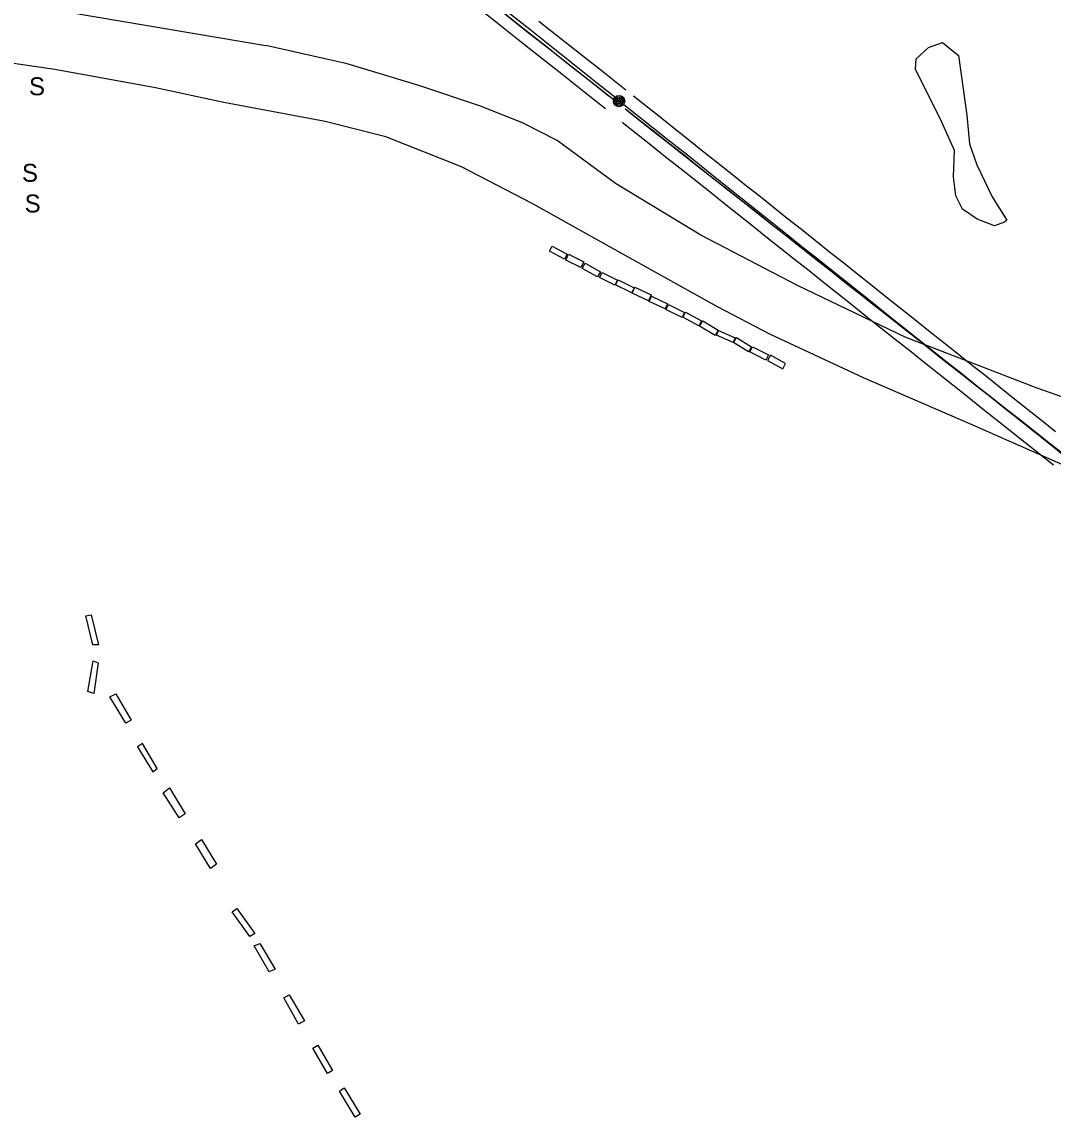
# Model space of a CAD drawing. Extents: x 368532 to 392481, y 10654822 to 10676899.
# Drawn here: x 372438.5 to 372783.2, y 10672184.9 to 10672551 of the extents above; entities that cross this region are included whole.
import ezdxf

# ---------------------------------------------------------------- set-up
doc = ezdxf.new("R2010")
doc.units = 0
for name, color, linetype in [('p_Catenary', 7, 'Continuous'), ('p_road conc barrier', 7, 'Continuous'), ('p_road dirt road', 7, 'Continuous'), ('p_structure sign', 7, 'Continuous'), ('p_utility general pole', 7, 'Continuous'), ('p_veg woods', 7, 'Continuous')]:
    doc.layers.add(name, color=color, linetype=linetype)

msp = doc.modelspace()

# ---------------------------------------------------------------- linework, layer by layer
at = {"layer": 'p_Catenary'}
for points in [[(372589.86, 10672556.62), (372597.14, 10672550.86), (372604.42, 10672545.1), (372611.7, 10672539.34), (372618.97, 10672533.59), (372626.25, 10672527.83), (372633.53, 10672522.07)], [(372598.88, 10672554.61), (372606.07, 10672548.92), (372613.25, 10672543.24), (372620.44, 10672537.55), (372627.62, 10672531.86), (372634.81, 10672526.18)], [(372599.9, 10672553.62), (372607.2, 10672547.88), (372614.51, 10672542.14), (372621.81, 10672536.41), (372629.12, 10672530.67), (372636.42, 10672524.94)], [(372601.61, 10672553.79), (372608.83, 10672548.05), (372616.04, 10672542.32), (372623.26, 10672536.58), (372630.48, 10672530.84), (372637.69, 10672525.1)], [(372611.33, 10672551.21), (372618.6, 10672545.48), (372625.88, 10672539.74), (372633.15, 10672534.01), (372640.42, 10672528.27)], [(372642.96, 10672526.25), (372651.83, 10672519.2), (372656.56, 10672515.44), (372661.28, 10672511.69), (372666, 10672507.93), (372670.72, 10672504.18), (372675.44, 10672500.42), (372680.16, 10672496.67), (372684.88, 10672492.91), (372689.61, 10672489.16), (372694.33, 10672485.4), (372699.05, 10672481.65), (372703.77, 10672477.89), (372708.49, 10672474.14), (372713.21, 10672470.38), (372717.94, 10672466.63), (372722.66, 10672462.87), (372727.38, 10672459.11), (372732.1, 10672455.36), (372736.82, 10672451.6), (372741.54, 10672447.85), (372746.27, 10672444.09), (372750.99, 10672440.34), (372755.71, 10672436.58), (372760.43, 10672432.83), (372765.15, 10672429.07), (372769.87, 10672425.32), (372774.6, 10672421.56), (372779.32, 10672417.81), (372784.04, 10672414.05)], [(372639.71, 10672523.41), (372644.63, 10672519.49), (372649.54, 10672515.57), (372654.46, 10672511.65), (372659.37, 10672507.73), (372664.28, 10672503.82), (372669.2, 10672499.9), (372674.11, 10672495.98), (372679.03, 10672492.06), (372683.94, 10672488.14), (372688.86, 10672484.22), (372693.77, 10672480.31), (372698.68, 10672476.39), (372703.6, 10672472.47), (372708.51, 10672468.55), (372713.43, 10672464.63), (372718.34, 10672460.72), (372723.26, 10672456.8), (372728.17, 10672452.88), (372733.09, 10672448.96), (372738, 10672445.04), (372742.91, 10672441.12), (372747.83, 10672437.21), (372752.74, 10672433.29), (372757.66, 10672429.37), (372762.57, 10672425.45), (372767.49, 10672421.53), (372772.4, 10672417.62), (372777.31, 10672413.7), (372782.23, 10672409.78), (372787.14, 10672405.86)], [(372640.14, 10672521.87), (372645.05, 10672518.01), (372649.95, 10672514.15), (372654.85, 10672510.29), (372659.75, 10672506.43), (372664.65, 10672502.57), (372669.56, 10672498.72), (372674.46, 10672494.86), (372679.36, 10672491), (372684.26, 10672487.14), (372689.16, 10672483.28), (372694.07, 10672479.42), (372698.97, 10672475.56), (372703.87, 10672471.71), (372708.77, 10672467.85), (372713.67, 10672463.99), (372718.58, 10672460.13), (372723.48, 10672456.27), (372728.38, 10672452.41), (372733.28, 10672448.56), (372738.18, 10672444.7), (372743.08, 10672440.84), (372747.99, 10672436.98), (372752.89, 10672433.12), (372757.79, 10672429.26), (372762.69, 10672425.4), (372767.59, 10672421.55), (372772.5, 10672417.69), (372777.4, 10672413.83), (372782.3, 10672409.97), (372787.2, 10672406.11)], [(372786.84, 10672406.15), (372781.96, 10672410), (372777.08, 10672413.85), (372772.2, 10672417.7), (372767.32, 10672421.55), (372762.44, 10672425.4), (372757.56, 10672429.25), (372752.67, 10672433.1), (372747.79, 10672436.95), (372742.91, 10672440.81), (372738.03, 10672444.66), (372733.15, 10672448.51), (372728.27, 10672452.36), (372723.39, 10672456.21), (372718.5, 10672460.06), (372713.62, 10672463.91), (372708.74, 10672467.76), (372703.86, 10672471.61), (372698.98, 10672475.46), (372694.1, 10672479.31), (372689.22, 10672483.16), (372684.33, 10672487.01), (372679.45, 10672490.86), (372674.57, 10672494.71), (372669.69, 10672498.56), (372664.81, 10672502.41), (372659.93, 10672506.26), (372655.05, 10672510.11), (372650.16, 10672513.97), (372645.28, 10672517.82), (372640.4, 10672521.67)], [(372639.15, 10672517.47), (372643.95, 10672513.65), (372648.76, 10672509.84), (372653.56, 10672506.02), (372658.37, 10672502.2), (372663.17, 10672498.38), (372667.98, 10672494.56), (372672.78, 10672490.74), (372677.58, 10672486.92), (372682.39, 10672483.1), (372687.19, 10672479.28), (372692, 10672475.46), (372696.8, 10672471.64), (372701.61, 10672467.82), (372706.41, 10672464), (372711.22, 10672460.18), (372716.02, 10672456.36), (372720.83, 10672452.55), (372725.63, 10672448.73), (372730.43, 10672444.91), (372735.24, 10672441.09), (372740.04, 10672437.27), (372744.85, 10672433.45), (372749.65, 10672429.63), (372754.46, 10672425.81), (372759.26, 10672421.99), (372764.07, 10672418.17), (372768.87, 10672414.35), (372773.68, 10672410.53), (372778.48, 10672406.71), (372783.28, 10672402.89)]]:
    msp.add_lwpolyline(points, dxfattribs=at)
at = {"layer": 'p_road conc barrier'}
for p, q in [((372614.82, 10672474.29), (372615.72, 10672475.99)), ((372619.84, 10672471.62), (372614.82, 10672474.29)), ((372615.72, 10672475.99), (372620.74, 10672473.32)), ((372620.74, 10672473.32), (372619.84, 10672471.62)), ((372620.26, 10672471.36), (372621.23, 10672473.29)), ((372625.3, 10672468.83), (372620.26, 10672471.36)), ((372621.23, 10672473.29), (372626.28, 10672470.76)), ((372626.28, 10672470.76), (372625.3, 10672468.83)), ((372625.78, 10672468.57), (372626.75, 10672470.3)), ((372626.75, 10672470.3), (372631.85, 10672467.45)), ((372630.88, 10672465.72), (372625.78, 10672468.57)), ((372631.85, 10672467.45), (372630.88, 10672465.72)), ((372631.6, 10672465.55), (372632.45, 10672467.23)), ((372632.45, 10672467.23), (372637.55, 10672464.64)), ((372636.69, 10672462.96), (372631.6, 10672465.55)), ((372637.55, 10672464.64), (372636.69, 10672462.96)), ((372636.96, 10672463.07), (372637.82, 10672464.79)), ((372642.32, 10672460.38), (372636.96, 10672463.07)), ((372637.82, 10672464.79), (372643.18, 10672462.1)), ((372643.18, 10672462.1), (372642.32, 10672460.38)), ((372642.5, 10672460.31), (372643.41, 10672462.26)), ((372647.91, 10672457.78), (372642.5, 10672460.31)), ((372643.41, 10672462.26), (372648.82, 10672459.73)), ((372648.82, 10672459.73), (372647.91, 10672457.78)), ((372648.18, 10672457.52), (372648.99, 10672459.25)), ((372648.99, 10672459.25), (372654.29, 10672456.77)), ((372653.49, 10672455.04), (372648.18, 10672457.52)), ((372654.29, 10672456.77), (372653.49, 10672455.04)), ((372653.78, 10672454.86), (372654.59, 10672456.5)), ((372654.59, 10672456.5), (372659.97, 10672453.84)), ((372659.17, 10672452.2), (372653.78, 10672454.86)), ((372659.97, 10672453.84), (372659.17, 10672452.2)), ((372659.45, 10672452.28), (372660.34, 10672453.9)), ((372664.77, 10672449.38), (372659.45, 10672452.28)), ((372660.34, 10672453.9), (372665.65, 10672451)), ((372665.65, 10672451), (372664.77, 10672449.38)), ((372664.98, 10672449.23), (372666.05, 10672451.04)), ((372670.22, 10672446.14), (372664.98, 10672449.23)), ((372666.05, 10672451.04), (372671.28, 10672447.96)), ((372671.28, 10672447.96), (372670.22, 10672446.14)), ((372670.64, 10672446.26), (372671.34, 10672447.84)), ((372676.2, 10672443.78), (372670.64, 10672446.26)), ((372671.34, 10672447.84), (372676.91, 10672445.37)), ((372676.91, 10672445.37), (372676.2, 10672443.78)), ((372676.33, 10672443.81), (372677.35, 10672445.46)), ((372677.35, 10672445.46), (372682.37, 10672442.37)), ((372681.36, 10672440.72), (372676.33, 10672443.81)), ((372682.37, 10672442.37), (372681.36, 10672440.72)), ((372681.84, 10672440.63), (372682.71, 10672442.36)), ((372682.71, 10672442.36), (372688.02, 10672439.67)), ((372687.15, 10672437.94), (372681.84, 10672440.63)), ((372688.02, 10672439.67), (372687.15, 10672437.94)), ((372688.67, 10672439.52), (372687.73, 10672437.75)), ((372687.73, 10672437.75), (372692.86, 10672435.03)), ((372693.79, 10672436.8), (372688.67, 10672439.52)), ((372692.86, 10672435.03), (372693.79, 10672436.8)), ((372459.83, 10672352.39), (372461.7, 10672352.75)), ((372462.16, 10672342.75), (372459.83, 10672352.39)), ((372461.7, 10672352.75), (372464.07, 10672342.73)), ((372464.07, 10672342.73), (372462.16, 10672342.75)), ((372460.53, 10672327.13), (372462.34, 10672337.35)), ((372462.34, 10672337.35), (372464, 10672336.75)), ((372464, 10672336.75), (372462.49, 10672326.47)), ((372462.49, 10672326.47), (372460.53, 10672327.13)), ((372467.91, 10672325.35), (372469.84, 10672326.31)), ((372473.19, 10672316.57), (372467.91, 10672325.35)), ((372469.84, 10672326.31), (372475.05, 10672317.53)), ((372475.05, 10672317.53), (372473.19, 10672316.57)), ((372478.78, 10672309.77), (372477.16, 10672308.64)), ((372483.74, 10672301.35), (372478.78, 10672309.77)), ((372477.16, 10672308.64), (372482.21, 10672300.25)), ((372482.21, 10672300.25), (372483.74, 10672301.35)), ((372485.74, 10672293.32), (372487.87, 10672294.91)), ((372487.87, 10672294.91), (372493.05, 10672286.28)), ((372491.04, 10672284.87), (372485.74, 10672293.32)), ((372493.05, 10672286.28), (372491.04, 10672284.87)), ((372496.55, 10672276.22), (372498.52, 10672277.66)), ((372501.54, 10672267.94), (372496.55, 10672276.22)), ((372498.52, 10672277.66), (372503.49, 10672269.41)), ((372503.49, 10672269.41), (372501.54, 10672267.94)), ((372508.77, 10672253.53), (372510.33, 10672254.6)), ((372510.33, 10672254.6), (372516.31, 10672246.25)), ((372514.72, 10672245.21), (372508.77, 10672253.53)), ((372516.31, 10672246.25), (372514.72, 10672245.21)), ((372516.15, 10672242.07), (372518.08, 10672242.85)), ((372521.18, 10672233.41), (372516.15, 10672242.07)), ((372518.08, 10672242.85), (372523.2, 10672234.28)), ((372523.2, 10672234.28), (372521.18, 10672233.41)), ((372526, 10672224.71), (372527.86, 10672225.73)), ((372527.86, 10672225.73), (372532.95, 10672217.07)), ((372530.94, 10672215.9), (372526, 10672224.71)), ((372532.95, 10672217.07), (372530.94, 10672215.9)), ((372535.78, 10672207.89), (372537.41, 10672208.97)), ((372540.63, 10672199.46), (372535.78, 10672207.89)), ((372537.41, 10672208.97), (372542.37, 10672200.42)), ((372542.37, 10672200.42), (372540.63, 10672199.46)), ((372544.71, 10672193.53), (372546.22, 10672194.67)), ((372549.86, 10672184.87), (372544.71, 10672193.53)), ((372546.22, 10672194.67), (372551.61, 10672185.89)), ((372551.61, 10672185.89), (372549.86, 10672184.87))]:
    msp.add_line(p, q, dxfattribs=at)
at = {"layer": 'p_road dirt road'}
for p, q in [((372446.84, 10672555.46), (372520.03, 10672543.11)), ((372449.52, 10672535.01), (372414.52, 10672540.22)), ((372547.22, 10672536.92), (372520.03, 10672543.11)), ((372571.17, 10672529.74), (372547.22, 10672536.92)), ((372483.12, 10672528.91), (372449.52, 10672535.01)), ((372505.96, 10672524.07), (372483.12, 10672528.91)), ((372591.82, 10672522.86), (372571.17, 10672529.74)), ((372539.88, 10672517.73), (372505.96, 10672524.07)), ((372605.82, 10672517.29), (372591.82, 10672522.86)), ((372560.17, 10672512.61), (372539.88, 10672517.73)), ((372617.46, 10672511.29), (372605.82, 10672517.29)), ((372585.42, 10672502.53), (372560.17, 10672512.61)), ((372636.88, 10672496.98), (372617.46, 10672511.29)), ((372609.07, 10672490.29), (372585.42, 10672502.53)), ((372665.46, 10672479.64), (372636.88, 10672496.98)), ((372634.74, 10672475.95), (372609.07, 10672490.29)), ((372697.8, 10672462.91), (372665.46, 10672479.64)), ((372671.02, 10672455.76), (372634.74, 10672475.95)), ((372733.77, 10672445.55), (372697.8, 10672462.91)), ((372688.49, 10672446.55), (372671.02, 10672455.76)), ((372719.8, 10672432.04), (372688.49, 10672446.55)), ((372777.88, 10672428.56), (372733.77, 10672445.55)), ((372756.13, 10672416.27), (372719.8, 10672432.04)), ((372820.2, 10672413.41), (372777.88, 10672428.56)), ((372788.48, 10672402.05), (372756.13, 10672416.27))]:
    msp.add_line(p, q, dxfattribs=at)
at = {"layer": 'p_utility general pole'}
for radius in [1.9, 1.44, 0.973, 0.539, 0.192]:
    msp.add_circle((372638.09, 10672524.52), radius, dxfattribs=at)
at = {"layer": 'p_veg woods'}
msp.add_lwpolyline([(372763.62, 10672482.85), (372757.75, 10672485.04), (372752.91, 10672488.42), (372750.62, 10672492.8), (372750.33, 10672495.66), (372749.84, 10672499.18), (372750.19, 10672507.94), (372746.04, 10672517.46), (372737.17, 10672535.22), (372737.4, 10672538.63), (372741.52, 10672542.41), (372746.21, 10672544.05), (372751.52, 10672539.76), (372754.34, 10672519.79), (372755.29, 10672510.25), (372757.69, 10672503.18), (372762.82, 10672492.49), (372767.77, 10672484.72), (372766.95, 10672484.05)], close=True, dxfattribs=at)

# ---------------------------------------------------------------- texts
at = {"layer": 'p_structure sign'}
for p in [(372440.86, 10672526.45), (372438.52, 10672497.52), (372439.42, 10672487.27)]:
    msp.add_text('S', height=6, dxfattribs=at).set_placement(p)

doc.saveas('drawing.dxf')
